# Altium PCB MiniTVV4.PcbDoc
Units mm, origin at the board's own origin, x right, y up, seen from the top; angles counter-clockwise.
Board outline 57.3 x 61.11 mm, 2 copper layers (Top Layer, Bottom Layer), stack 1.571 mm thick; 6 components, 14 nets, 59 pads, 1169 vias.
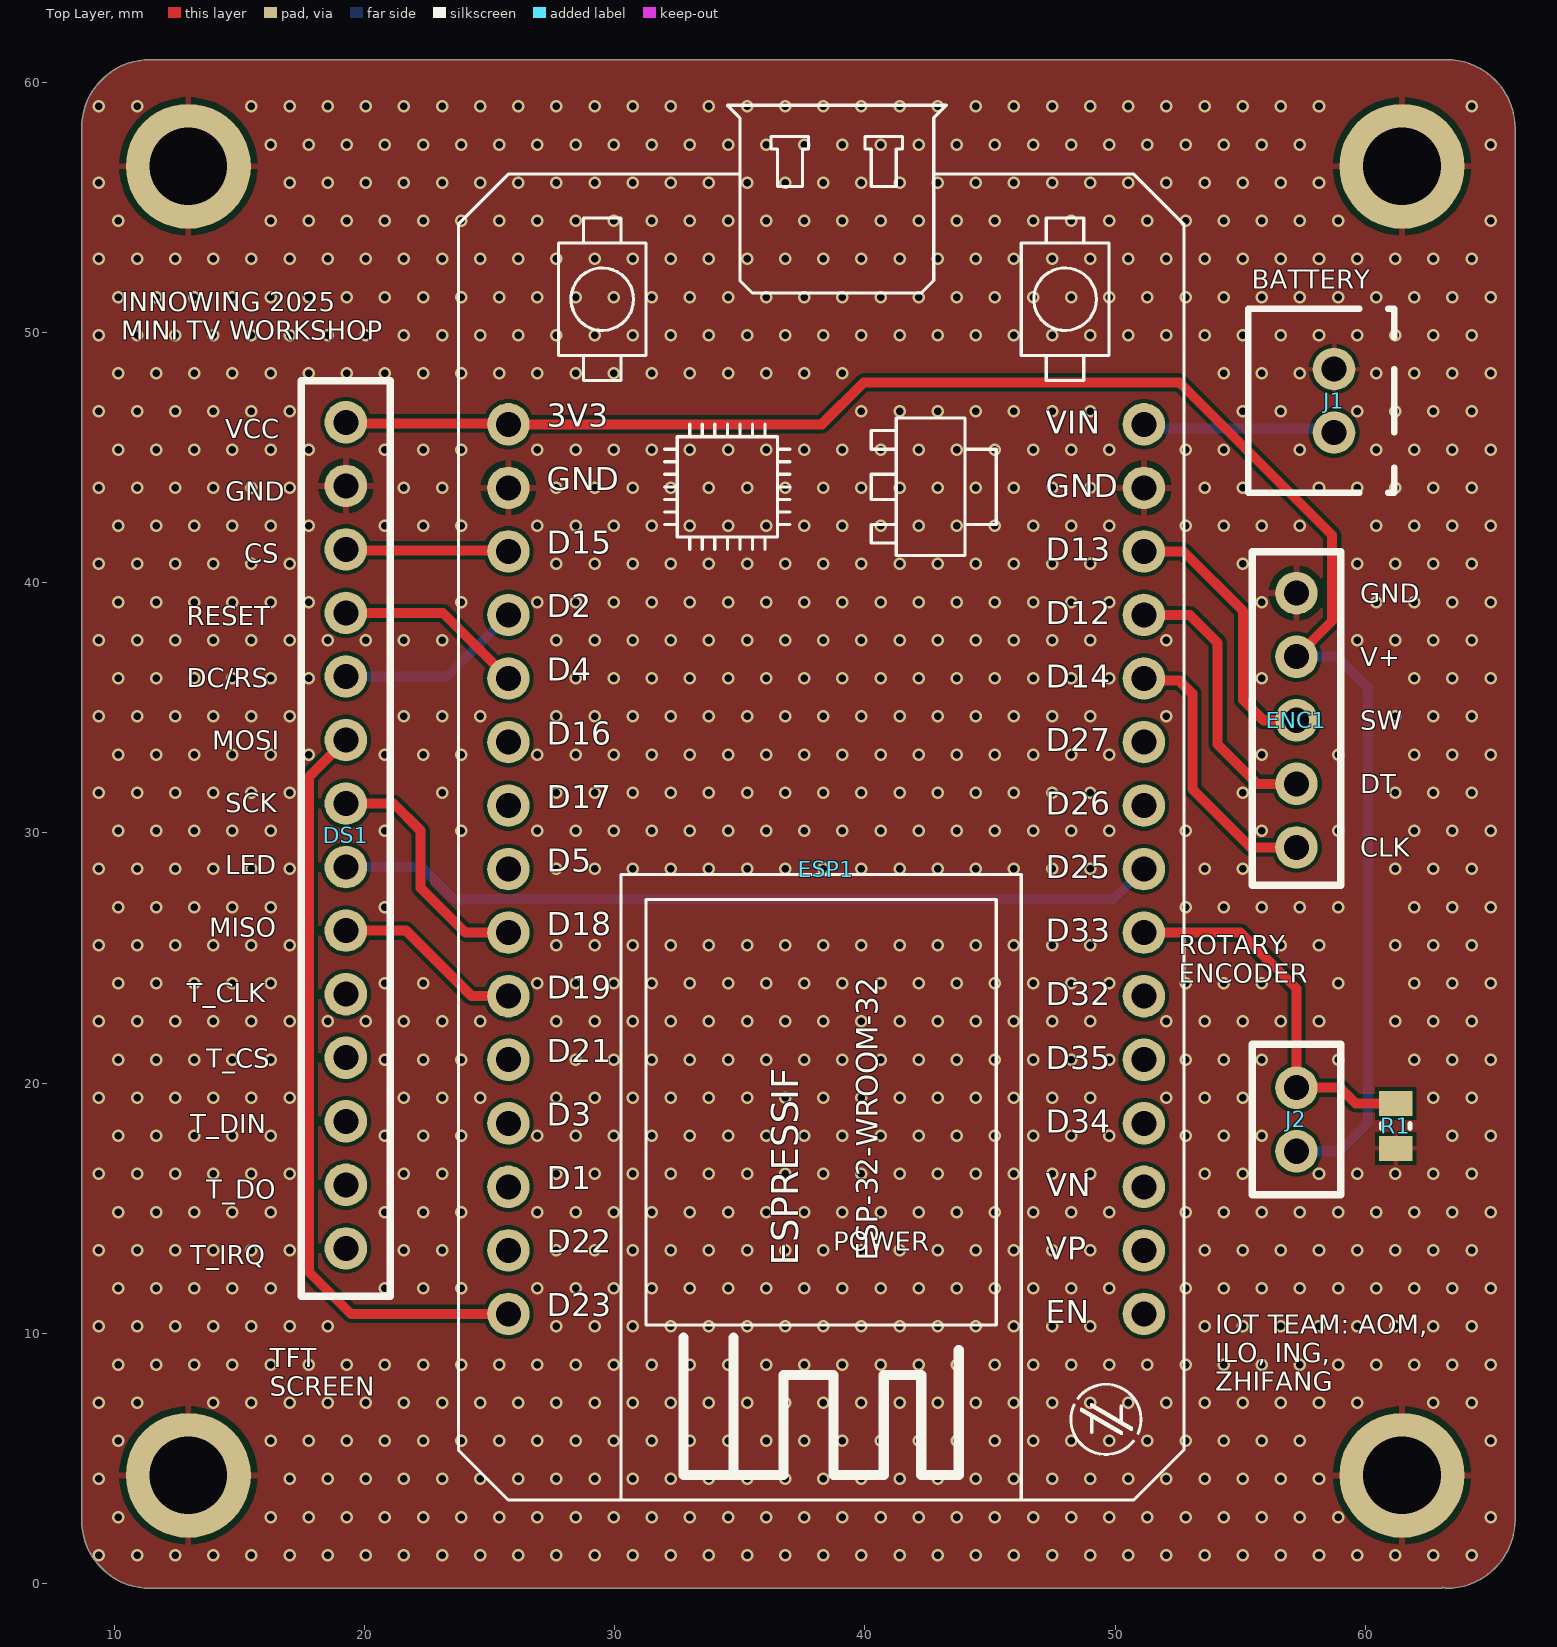
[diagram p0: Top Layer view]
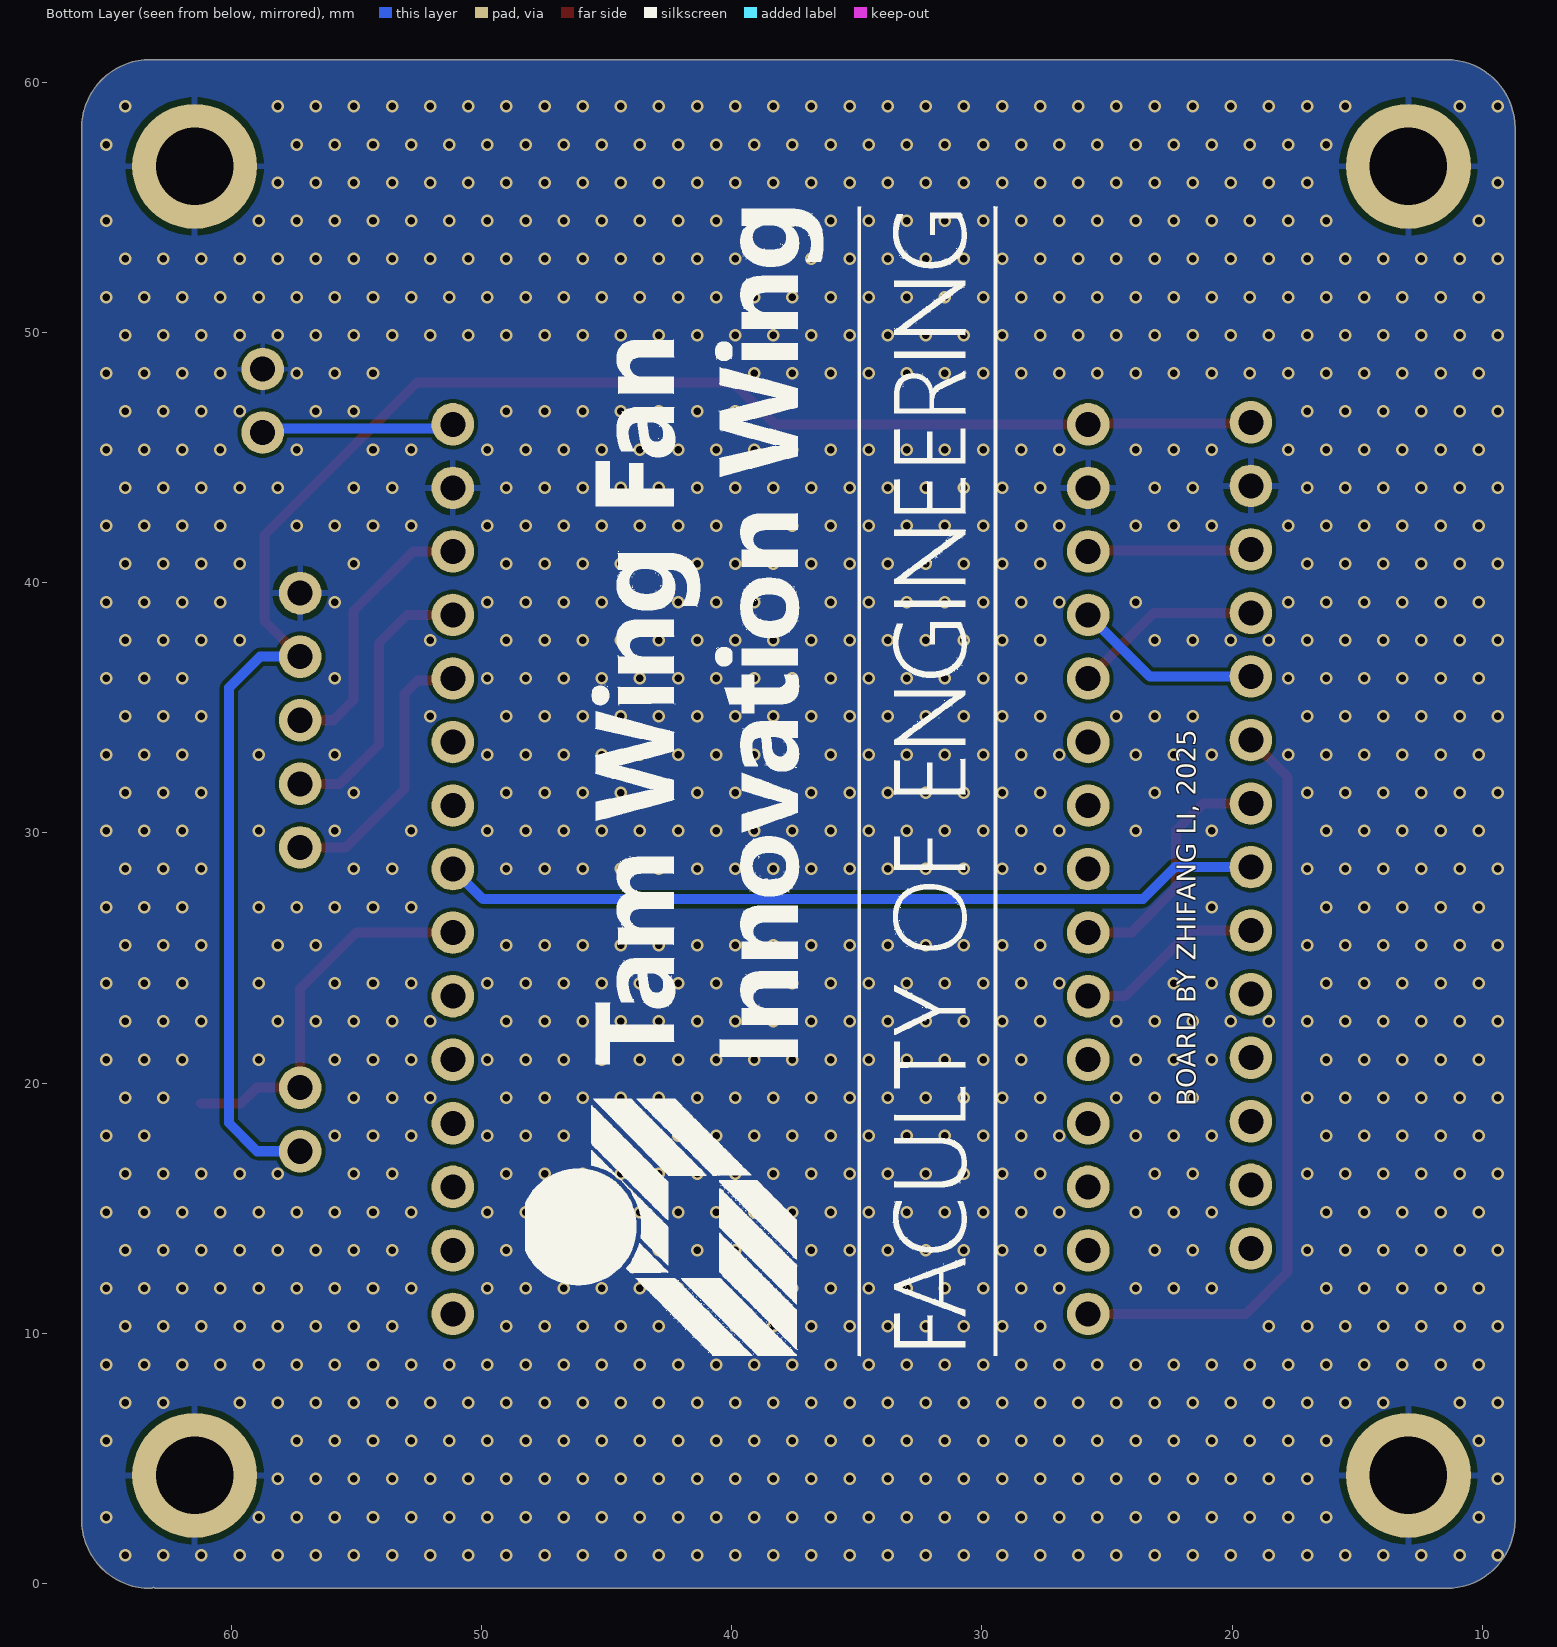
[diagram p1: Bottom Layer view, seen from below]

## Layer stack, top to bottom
Top Solder: solder mask 0.0102, Solder Resist, Dk 3.5
Top Layer: signal copper 0.0356
Dielectric 1: dielectric 1.5, FR-4, Dk 4.8
Bottom Layer: signal copper 0.0356
Bottom Solder: solder mask 0.0102, Solder Resist, Dk 3.5

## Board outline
8.69,2.54 ccw(c11.43,2.54) 11.43,-0.2 62.992,-0.2 ccw(c62.992,0) 63.119,-0.155 ccw(c63.246,0) 63.246,-0.2 ccw(c63.246,2.54) 65.986,2.539 65.986,2.54 65.986,58.166 65.986,58.167 ccw(c63.246,58.166) 63.246,60.906 11.43,60.906 ccw(c11.43,58.166) 8.69,58.166

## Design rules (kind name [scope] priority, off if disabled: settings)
Clearance [All] p1: gap=0.15 ignorepadtopadclearanceinfootprint=FALSE
DiffPairsRouting [All] p1: maxlimit=1 minlimit=0.127 mostfreqgap=0.2 toplayer_minwidth=0.127 toplayer_maxwidth=0.2 toplayer_prefwidth=0.2 bottomlayer_minwidth=0.127 bottomlayer_maxwidth=0.2 bottomlayer_prefwidth=0.2 maxuncoupledlength=12.7
Height [All] p1: minheight=0 maxheight=500 prefheight=12.7
HoleSize [All] p1: absolutevalues=TRUE maxlimit=6.3 minlimit=0.025 maxpercent=80.000 minpercent=20.000
MinimumSolderMaskSliver [All] p1: minsoldermaskwidth=0.04
PolygonConnect CertainComponents [InComponent('C0','C00') vs InNet('GND')] p1: connectstyle=Direct reliefconductorwidth=0.2 reliefentries=4 polygonreliefangle="90 Angle" airgapwidth=0.2 // force certain component to be conencted with relieft connection
PolygonConnect GND [InNet('GND')] p2: thpad.connectstyle=Relief thpad.reliefconductorwidth=0.2 thpad.reliefentries=4 thpad.polygonreliefangle="90 Angle" thpad.airgapwidth=0.15 smdpad.connectstyle=Relief smdpad.reliefconductorwidth=0.2 smdpad.reliefentries=4 smdpad.polygonreliefangle="90 Angle" smdpad.airgapwidth=0.15 via.connectstyle=Direct via.reliefconductorwidth=0.254 via.reliefentries=4 via.polygonreliefangle="90 Angle" via.airgapwidth=0.254
PolygonConnect [All] p3: connectstyle=Direct reliefconductorwidth=0.3 reliefentries=4 polygonreliefangle="90 Angle" airgapwidth=0.127
RoutingVias [All] p1: holewidth=0.3 width=0.5 viastyle="Through Hole" minholewidth=0.3 minwidth=0.5 maxholewidth=6 maxwidth=6.3
SilkToSilkClearance [All] p1: silktosilkclearance=0.04
SilkToSolderMaskClearance [IsPad] p1: minsilkscreentomaskgap=0.04 clearancetoexposedcopper=TRUE
SolderMaskExpansion [All] p1: expansion=0.102 istentingtop=FALSE
SupplyNets "Schematic Supply Nets" [InNet('5V')] p1: voltage=0.000
SupplyNets "Schematic Supply Nets_4" [InNet('3V3')] p2: voltage=0.000
SupplyNets "Schematic Supply Nets_3" [InNet('GND')] p3: voltage=0.000
Width [All] p1: maxlimit=3 minlimit=0.127 preferedwidth=0.2
24 further rules are at their usual default settings.

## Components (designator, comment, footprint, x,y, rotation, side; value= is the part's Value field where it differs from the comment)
DS1 "3.5inch TFT Display" "3.5inch SPI Display" 19.25,46.41 r0 top
ENC1 "Rotary Encoder" "Rotary Encoder" 57.25,29.42 r180 top
ESP1 "https://github.com/shridattdudhat" ESP32-DEVKITV1 25.75,46.33 r270 top
J1 "JST_XH_2P_2.54mm" JST_XH_2P_2.54mm 58.75,47.27 r90 top
J2 "Undifferentiated Pins" "2-Pin 2.54mm" 57.25,18.542 r90 top
R1 "10k 0805" RESC2013X60X35NL10T20 61.214,18.288 r90 top

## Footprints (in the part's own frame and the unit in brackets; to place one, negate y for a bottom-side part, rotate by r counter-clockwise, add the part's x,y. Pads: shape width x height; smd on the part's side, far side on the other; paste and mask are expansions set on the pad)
"2-Pin 2.54mm" [mm]
  round 1.7 hole 1 paste-2539.97 mask+0.051: 1(-1.27,0) 2(1.27,0)
  silkscreen extent -3,-1.78 3,1.78
"3.5inch SPI Display" [mm]
  round 1.7 hole 1: 1(0,0) 2(0,-2.54) 3(0,-5.08) 4(0,-7.62) 5(0,-10.16) 6(0,-12.7) 7(0,-15.24) 8(0,-17.78) 9(0,-20.32) 10(0,-22.86) 11(0,-25.4) 12(0,-27.94) 13(0,-30.48) 14(0,-33.02)
  silkscreen extent -1.78,-34.92 1.78,1.65
ESP32-DEVKITV1 [mm]
  round 1.7 hole 1: 3V3(0,0) D1(30.48,0) D2(7.62,0) D3(27.94,0) D4(10.16,0) D5(17.78,0) D12(7.62,25.4) D13(5.08,25.4) D14(10.16,25.4) D15(5.08,0) D16(12.7,0) D17(15.24,0) D18(20.32,0) D19(22.86,0) D21(25.4,0) D22(33.02,0) D23(35.56,0) D25(17.78,25.4) D26(15.24,25.4) D27(12.7,25.4) D32(22.86,25.4) D33(20.32,25.4) D34(27.94,25.4) D35(25.4,25.4) EN(35.56,25.4) GND(2.54,25.4) GND@1(2.54,0) VIN(0,25.4) VN(30.48,25.4) VP(33.02,25.4)
  silkscreen extent -12.75,-2 43,27
JST_XH_2P_2.54mm [mm]
  round 1.7 hole 1 paste-2539.97 mask+0.051: 1(-1.27,0) 2(1.27,0)
  silkscreen extent -3.68,-2.41 3.68,3.43
RESC2013X60X35NL10T20 [mm] "Chip Resistor, 2-Leads, Body 2.00x1.25mm, IPC Medium Density"
  rect 1x1.35 smd: 1(-0.9,0) 2(0.9,0)
  silkscreen extent -0.1,-0.58 0.1,0.58, body extent -1.05,-0.67 1.05,0.67, height 0.6
"Rotary Encoder" [mm]
  round 1.7 hole 1: 1(0,0) 2(0,-2.54) 3(0,-5.08) 4(0,-7.62) 5(0,-10.16)
  silkscreen extent -1.78,-11.81 1.78,1.52

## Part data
ESP1: library part ESP32DEVKITV1, Package=ESP32-DEVKITV1
J2: library part "SPST 2-Pin"
R1: library part CMP-2001-04523-1, Manufacturer=Yageo, Part Number=RC0805FR-104K7L

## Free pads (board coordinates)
  round 5 hole 3.1: MNT(12.954,4.318) MNT(12.954,56.642) MNT(61.468,4.318) MNT(61.468,56.642)

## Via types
v1: diameter 0.5, hole 0.3, Top Layer to Bottom Layer, tented both sides, 1169 vias

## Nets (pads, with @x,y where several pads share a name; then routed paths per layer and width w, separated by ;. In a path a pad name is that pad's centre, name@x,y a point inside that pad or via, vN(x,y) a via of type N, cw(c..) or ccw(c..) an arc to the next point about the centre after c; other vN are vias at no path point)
3V3: DS1.1 ENC1.4 ESP1.3V3 J2.1 | length 72.2
  Top Layer w0.4: DS1.1 19.29,46.37 25.71,46.37 ESP1.3V3 38.274,46.33 39.95,48.006 52.578,48.006 58.674,41.91 58.674,38.464 ENC1.4
  Bottom Layer w0.4: J2.1 58.972,17.272 60.1,18.4 60.1,35.8 58.86,37.04 ENC1.4
5V: ESP1.VIN J1.1 | length 7.7
  Bottom Layer w0.4: ESP1.VIN 51.315,46.165 58.585,46.165 J1.1
GND: DS1.2 ENC1.5 ESP1.GND ESP1.GND@1 J1.2 pad.MNT R1.1
  other v1: 9.382,1.124 10.906,1.124 12.43,1.124 13.954,1.124 15.478,1.124 17.002,1.124 18.526,1.124 20.05,1.124 21.574,1.124 23.098,1.124 24.622,1.124 26.146,1.124 27.67,1.124 29.194,1.124 30.718,1.124 32.242,1.124 33.766,1.124 35.29,1.124 36.814,1.124 38.338,1.124 39.862,1.124 41.386,1.124 42.91,1.124 44.434,1.124 45.958,1.124 47.482,1.124 49.006,1.124 50.53,1.124 52.054,1.124 53.578,1.124 55.102,1.124 56.626,1.124 58.15,1.124 59.674,1.124 61.198,1.124 62.722,1.124 64.246,1.124 10.144,2.648 16.24,2.648 17.764,2.648 19.288,2.648 20.812,2.648 22.336,2.648 23.86,2.648 25.384,2.648 26.908,2.648 28.432,2.648 29.956,2.648 31.48,2.648 33.004,2.648 34.528,2.648 36.052,2.648 37.576,2.648 39.1,2.648 40.624,2.648 42.148,2.648 43.672,2.648 45.196,2.648 46.72,2.648 48.244,2.648 49.768,2.648 51.292,2.648 52.816,2.648 54.34,2.648 55.864,2.648 57.388,2.648 58.912,2.648 65.008,2.648 9.382,4.172 17.002,4.172 18.526,4.172 20.05,4.172 21.574,4.172 23.098,4.172 24.622,4.172 26.146,4.172 27.67,4.172 29.194,4.172 30.718,4.172 32.242,4.172 33.766,4.172 35.29,4.172 36.814,4.172 38.338,4.172 39.862,4.172 41.386,4.172 42.91,4.172 44.434,4.172 45.958,4.172 47.482,4.172 49.006,4.172 50.53,4.172 52.054,4.172 53.578,4.172 55.102,4.172 56.626,4.172 58.15,4.172 10.144,5.696 16.24,5.696 17.764,5.696 19.288,5.696 20.812,5.696 22.336,5.696 23.86,5.696 25.384,5.696 26.908,5.696 28.432,5.696 29.956,5.696 31.48,5.696 33.004,5.696 34.528,5.696 36.052,5.696 37.576,5.696 39.1,5.696 40.624,5.696 42.148,5.696 43.672,5.696 45.196,5.696 46.72,5.696 48.244,5.696 49.768,5.696 51.292,5.696 52.816,5.696 54.34,5.696 55.864,5.696 57.388,5.696 65.008,5.696 9.382,7.22 10.906,7.22 13.954,7.22 15.478,7.22 17.002,7.22 18.526,7.22 20.05,7.22 21.574,7.22 23.098,7.22 24.622,7.22 26.146,7.22 27.67,7.22 29.194,7.22 30.718,7.22 32.242,7.22 33.766,7.22 35.29,7.22 36.814,7.22 38.338,7.22 39.862,7.22 41.386,7.22 42.91,7.22 44.434,7.22 45.958,7.22 47.482,7.22 49.006,7.22 50.53,7.22 52.054,7.22 53.578,7.22 55.102,7.22 56.626,7.22 58.15,7.22 59.674,7.22 62.722,7.22 64.246,7.22 10.144,8.744 11.668,8.744 13.192,8.744 14.716,8.744 16.24,8.744 17.764,8.744 19.288,8.744 20.812,8.744 22.336,8.744 23.86,8.744 25.384,8.744 26.908,8.744 28.432,8.744 29.956,8.744 31.48,8.744 33.004,8.744 34.528,8.744 36.052,8.744 37.576,8.744 39.1,8.744 40.624,8.744 42.148,8.744 43.672,8.744 45.196,8.744 46.72,8.744 48.244,8.744 49.768,8.744 51.292,8.744 52.816,8.744 54.34,8.744 55.864,8.744 57.388,8.744 58.912,8.744 60.436,8.744 61.96,8.744 63.484,8.744 65.008,8.744 9.382,10.268 10.906,10.268 12.43,10.268 13.954,10.268 15.478,10.268 17.002,10.268 18.526,10.268 27.67,10.268 29.194,10.268 30.718,10.268 32.242,10.268 33.766,10.268 35.29,10.268 36.814,10.268 38.338,10.268 39.862,10.268 41.386,10.268 42.91,10.268 44.434,10.268 45.958,10.268 47.482,10.268 49.006,10.268 53.578,10.268 55.102,10.268 56.626,10.268 58.15,10.268 59.674,10.268 61.198,10.268 62.722,10.268 64.246,10.268 10.144,11.792 11.668,11.792 13.192,11.792 14.716,11.792 16.24,11.792 20.812,11.792 22.336,11.792 23.86,11.792 26.908,11.792 28.432,11.792 29.956,11.792 31.48,11.792 33.004,11.792 34.528,11.792 36.052,11.792 37.576,11.792 39.1,11.792 40.624,11.792 42.148,11.792 43.672,11.792 45.196,11.792 46.72,11.792 48.244,11.792 49.768,11.792 52.816,11.792 54.34,11.792 55.864,11.792 57.388,11.792 58.912,11.792 60.436,11.792 61.96,11.792 63.484,11.792 65.008,11.792 9.382,13.316 10.906,13.316 12.43,13.316 13.954,13.316 15.478,13.316 17.002,13.316 21.574,13.316 23.098,13.316 27.67,13.316 29.194,13.316 30.718,13.316 32.242,13.316 33.766,13.316 35.29,13.316 36.814,13.316 38.338,13.316 39.862,13.316 41.386,13.316 42.91,13.316 44.434,13.316 45.958,13.316 47.482,13.316 49.006,13.316 53.578,13.316 55.102,13.316 56.626,13.316 58.15,13.316 59.674,13.316 61.198,13.316 62.722,13.316 64.246,13.316 10.144,14.84 11.668,14.84 13.192,14.84 14.716,14.84 16.24,14.84 20.812,14.84 22.336,14.84 23.86,14.84 26.908,14.84 28.432,14.84 29.956,14.84 31.48,14.84 33.004,14.84 34.528,14.84 36.052,14.84 37.576,14.84 39.1,14.84 40.624,14.84 42.148,14.84 43.672,14.84 45.196,14.84 46.72,14.84 48.244,14.84 49.768,14.84 52.816,14.84 54.34,14.84 55.864,14.84 57.388,14.84 58.912,14.84 60.436,14.84 61.96,14.84 63.484,14.84 65.008,14.84 9.382,16.364 10.906,16.364 12.43,16.364 13.954,16.364 15.478,16.364 17.002,16.364 21.574,16.364 23.098,16.364 27.67,16.364 29.194,16.364 30.718,16.364 32.242,16.364 33.766,16.364 35.29,16.364 36.814,16.364 38.338,16.364 39.862,16.364 41.386,16.364 42.91,16.364 44.434,16.364 45.958,16.364 47.482,16.364 49.006,16.364 53.578,16.364 55.102,16.364 58.15,16.364 59.674,16.364 61.198,16.364 62.722,16.364 64.246,16.364 10.144,17.888 11.668,17.888 13.192,17.888 14.716,17.888 16.24,17.888 20.812,17.888 22.336,17.888 23.86,17.888 26.908,17.888 28.432,17.888 29.956,17.888 31.48,17.888 33.004,17.888 34.528,17.888 36.052,17.888 37.576,17.888 39.1,17.888 40.624,17.888 42.148,17.888 43.672,17.888 45.196,17.888 46.72,17.888 48.244,17.888 49.768,17.888 52.816,17.888 54.34,17.888 55.864,17.888 63.484,17.888 65.008,17.888 9.382,19.412 10.906,19.412 12.43,19.412 13.954,19.412 15.478,19.412 17.002,19.412 21.574,19.412 23.098,19.412 24.622,19.412 27.67,19.412 29.194,19.412 30.718,19.412 32.242,19.412 33.766,19.412 35.29,19.412 36.814,19.412 38.338,19.412 39.862,19.412 41.386,19.412 42.91,19.412 44.434,19.412 45.958,19.412 47.482,19.412 49.006,19.412 52.054,19.412 53.578,19.412 55.102,19.412 62.722,19.412 64.246,19.412 10.144,20.936 11.668,20.936 13.192,20.936 14.716,20.936 16.24,20.936 20.812,20.936 22.336,20.936 23.86,20.936 28.432,20.936 29.956,20.936 31.48,20.936 33.004,20.936 34.528,20.936 36.052,20.936 37.576,20.936 39.1,20.936 40.624,20.936 42.148,20.936 43.672,20.936 45.196,20.936 46.72,20.936 48.244,20.936 49.768,20.936 52.816,20.936 54.34,20.936 55.864,20.936 58.912,20.936 61.96,20.936 63.484,20.936 65.008,20.936 9.382,22.46 10.906,22.46 12.43,22.46 13.954,22.46 15.478,22.46 17.002,22.46 18.526,22.46 20.05,22.46 21.574,22.46 23.098,22.46 24.622,22.46 27.67,22.46 29.194,22.46 30.718,22.46 32.242,22.46 33.766,22.46 35.29,22.46 36.814,22.46 38.338,22.46 39.862,22.46 41.386,22.46 42.91,22.46 44.434,22.46 45.958,22.46 47.482,22.46 49.006,22.46 52.054,22.46 53.578,22.46 55.102,22.46 56.626,22.46 58.15,22.46 61.198,22.46 62.722,22.46 64.246,22.46 10.144,23.984 11.668,23.984 13.192,23.984 14.716,23.984 16.24,23.984 20.812,23.984 22.336,23.984 26.908,23.984 28.432,23.984 29.956,23.984 31.48,23.984 33.004,23.984 34.528,23.984 36.052,23.984 37.576,23.984 39.1,23.984 40.624,23.984 42.148,23.984 43.672,23.984 45.196,23.984 46.72,23.984 48.244,23.984 49.768,23.984 52.816,23.984 54.34,23.984 55.864,23.984 58.912,23.984 61.96,23.984 63.484,23.984 65.008,23.984 9.382,25.508 10.906,25.508 12.43,25.508 13.954,25.508 15.478,25.508 17.002,25.508 27.67,25.508 29.194,25.508 30.718,25.508 32.242,25.508 33.766,25.508 35.29,25.508 36.814,25.508 38.338,25.508 39.862,25.508 41.386,25.508 42.91,25.508 44.434,25.508 45.958,25.508 47.482,25.508 49.006,25.508 56.626,25.508 58.15,25.508 61.198,25.508 62.722,25.508 64.246,25.508 10.144,27.032 11.668,27.032 13.192,27.032 14.716,27.032 16.24,27.032 20.812,27.032 52.816,27.032 54.34,27.032 55.864,27.032 57.388,27.032 58.912,27.032 61.96,27.032 63.484,27.032 65.008,27.032 9.382,28.556 10.906,28.556 12.43,28.556 13.954,28.556 15.478,28.556 17.002,28.556 27.67,28.556 29.194,28.556 30.718,28.556 32.242,28.556 33.766,28.556 35.29,28.556 36.814,28.556 38.338,28.556 39.862,28.556 41.386,28.556 42.91,28.556 44.434,28.556 45.958,28.556 47.482,28.556 49.006,28.556 53.578,28.556 55.102,28.556 61.198,28.556 62.722,28.556 64.246,28.556 10.144,30.08 11.668,30.08 13.192,30.08 14.716,30.08 16.24,30.08 20.812,30.08 23.86,30.08 26.908,30.08 28.432,30.08 29.956,30.08 31.48,30.08 33.004,30.08 34.528,30.08 36.052,30.08 37.576,30.08 39.1,30.08 40.624,30.08 42.148,30.08 43.672,30.08 45.196,30.08 46.72,30.08 48.244,30.08 49.768,30.08 52.816,30.08 55.864,30.08 58.912,30.08 61.96,30.08 63.484,30.08 65.008,30.08 9.382,31.604 10.906,31.604 12.43,31.604 13.954,31.604 15.478,31.604 17.002,31.604 23.098,31.604 27.67,31.604 29.194,31.604 30.718,31.604 32.242,31.604 33.766,31.604 35.29,31.604 36.814,31.604 38.338,31.604 39.862,31.604 41.386,31.604 42.91,31.604 44.434,31.604 45.958,31.604 47.482,31.604 49.006,31.604 55.102,31.604 61.198,31.604 62.722,31.604 64.246,31.604 10.144,33.128 11.668,33.128 13.192,33.128 14.716,33.128 16.24,33.128 17.764,33.128 20.812,33.128 22.336,33.128 23.86,33.128 26.908,33.128 28.432,33.128 29.956,33.128 31.48,33.128 33.004,33.128 34.528,33.128 36.052,33.128 37.576,33.128 39.1,33.128 40.624,33.128 42.148,33.128 43.672,33.128 45.196,33.128 46.72,33.128 48.244,33.128 49.768,33.128 55.864,33.128 58.912,33.128 61.96,33.128 63.484,33.128 65.008,33.128 9.382,34.652 10.906,34.652 12.43,34.652 13.954,34.652 15.478,34.652 17.002,34.652 21.574,34.652 23.098,34.652 24.622,34.652 27.67,34.652 29.194,34.652 30.718,34.652 32.242,34.652 33.766,34.652 35.29,34.652 36.814,34.652 38.338,34.652 39.862,34.652 41.386,34.652 42.91,34.652 44.434,34.652 45.958,34.652 47.482,34.652 49.006,34.652 52.054,34.652 61.198,34.652 62.722,34.652 64.246,34.652 10.144,36.176 11.668,36.176 13.192,36.176 14.716,36.176 16.24,36.176 17.764,36.176 28.432,36.176 29.956,36.176 31.48,36.176 33.004,36.176 34.528,36.176 36.052,36.176 37.576,36.176 39.1,36.176 40.624,36.176 42.148,36.176 43.672,36.176 45.196,36.176 46.72,36.176 48.244,36.176 49.768,36.176 55.864,36.176 61.96,36.176 63.484,36.176 65.008,36.176 9.382,37.7 10.906,37.7 12.43,37.7 13.954,37.7 15.478,37.7 17.002,37.7 18.526,37.7 20.05,37.7 21.574,37.7 23.098,37.7 27.67,37.7 29.194,37.7 30.718,37.7 32.242,37.7 33.766,37.7 35.29,37.7 36.814,37.7 38.338,37.7 39.862,37.7 41.386,37.7 42.91,37.7 44.434,37.7 45.958,37.7 47.482,37.7 49.006,37.7 52.054,37.7 59.674,37.7 61.198,37.7 62.722,37.7 64.246,37.7 10.144,39.224 11.668,39.224 13.192,39.224 14.716,39.224 16.24,39.224 17.764,39.224 23.86,39.224 26.908,39.224 28.432,39.224 29.956,39.224 31.48,39.224 33.004,39.224 34.528,39.224 36.052,39.224 37.576,39.224 39.1,39.224 40.624,39.224 42.148,39.224 43.672,39.224 45.196,39.224 46.72,39.224 48.244,39.224 49.768,39.224 55.864,39.224 60.436,39.224 61.96,39.224 63.484,39.224 65.008,39.224 9.382,40.748 10.906,40.748 12.43,40.748 13.954,40.748 15.478,40.748 17.002,40.748 27.67,40.748 29.194,40.748 30.718,40.748 32.242,40.748 33.766,40.748 35.29,40.748 36.814,40.748 38.338,40.748 39.862,40.748 41.386,40.748 42.91,40.748 44.434,40.748 45.958,40.748 47.482,40.748 49.006,40.748 55.102,40.748 59.674,40.748 61.198,40.748 62.722,40.748 64.246,40.748 10.144,42.272 11.668,42.272 13.192,42.272 14.716,42.272 16.24,42.272 17.764,42.272 20.812,42.272 22.336,42.272 23.86,42.272 26.908,42.272 28.432,42.272 29.956,42.272 31.48,42.272 33.004,42.272 34.528,42.272 36.052,42.272 37.576,42.272 39.1,42.272 40.624,42.272 42.148,42.272 43.672,42.272 45.196,42.272 46.72,42.272 48.244,42.272 49.768,42.272 52.816,42.272 54.34,42.272 55.864,42.272 57.388,42.272 60.436,42.272 61.96,42.272 63.484,42.272 65.008,42.272 9.382,43.796 10.906,43.796 12.43,43.796 13.954,43.796 15.478,43.796 17.002,43.796 21.574,43.796 23.098,43.796 27.67,43.796 29.194,43.796 30.718,43.796 32.242,43.796 33.766,43.796 35.29,43.796 36.814,43.796 38.338,43.796 39.862,43.796 41.386,43.796 42.91,43.796 44.434,43.796 45.958,43.796 47.482,43.796 49.006,43.796 53.578,43.796 55.102,43.796 58.15,43.796 59.674,43.796 61.198,43.796 62.722,43.796 64.246,43.796 10.144,45.32 11.668,45.32 13.192,45.32 14.716,45.32 16.24,45.32 17.764,45.32 20.812,45.32 22.336,45.32 23.86,45.32 26.908,45.32 28.432,45.32 29.956,45.32 31.48,45.32 33.004,45.32 34.528,45.32 36.052,45.32 37.576,45.32 39.1,45.32 40.624,45.32 42.148,45.32 43.672,45.32 45.196,45.32 46.72,45.32 48.244,45.32 49.768,45.32 52.816,45.32 54.34,45.32 57.388,45.32 60.436,45.32 61.96,45.32 63.484,45.32 65.008,45.32 9.382,46.844 10.906,46.844 12.43,46.844 13.954,46.844 15.478,46.844 17.002,46.844 39.862,46.844 41.386,46.844 42.91,46.844 44.434,46.844 45.958,46.844 47.482,46.844 49.006,46.844 55.102,46.844 56.626,46.844 59.674,46.844 61.198,46.844 62.722,46.844 64.246,46.844 10.144,48.368 11.668,48.368 13.192,48.368 14.716,48.368 16.24,48.368 17.764,48.368 19.288,48.368 20.812,48.368 22.336,48.368 23.86,48.368 25.384,48.368 26.908,48.368 28.432,48.368 29.956,48.368 31.48,48.368 33.004,48.368 34.528,48.368 36.052,48.368 37.576,48.368 39.1,48.368 54.34,48.368 55.864,48.368 57.388,48.368 60.436,48.368 61.96,48.368 63.484,48.368 65.008,48.368 9.382,49.892 10.906,49.892 12.43,49.892 13.954,49.892 15.478,49.892 17.002,49.892 18.526,49.892 20.05,49.892 21.574,49.892 23.098,49.892 24.622,49.892 26.146,49.892 27.67,49.892 29.194,49.892 30.718,49.892 32.242,49.892 33.766,49.892 35.29,49.892 36.814,49.892 38.338,49.892 39.862,49.892 41.386,49.892 42.91,49.892 44.434,49.892 45.958,49.892 47.482,49.892 49.006,49.892 50.53,49.892 52.054,49.892 53.578,49.892 55.102,49.892 56.626,49.892 58.15,49.892 59.674,49.892 61.198,49.892 62.722,49.892 64.246,49.892 10.144,51.416 11.668,51.416 13.192,51.416 14.716,51.416 16.24,51.416 17.764,51.416 19.288,51.416 20.812,51.416 22.336,51.416 23.86,51.416 25.384,51.416 26.908,51.416 28.432,51.416 29.956,51.416 31.48,51.416 33.004,51.416 34.528,51.416 36.052,51.416 37.576,51.416 39.1,51.416 40.624,51.416 42.148,51.416 43.672,51.416 45.196,51.416 46.72,51.416 48.244,51.416 49.768,51.416 51.292,51.416 52.816,51.416 54.34,51.416 55.864,51.416 57.388,51.416 58.912,51.416 60.436,51.416 61.96,51.416 63.484,51.416 65.008,51.416 9.382,52.94 10.906,52.94 12.43,52.94 13.954,52.94 15.478,52.94 17.002,52.94 18.526,52.94 20.05,52.94 21.574,52.94 23.098,52.94 24.622,52.94 26.146,52.94 27.67,52.94 29.194,52.94 30.718,52.94 32.242,52.94 33.766,52.94 35.29,52.94 36.814,52.94 38.338,52.94 39.862,52.94 41.386,52.94 42.91,52.94 44.434,52.94 45.958,52.94 47.482,52.94 49.006,52.94 50.53,52.94 52.054,52.94 53.578,52.94 55.102,52.94 56.626,52.94 58.15,52.94 59.674,52.94 61.198,52.94 62.722,52.94 64.246,52.94 10.144,54.464 16.24,54.464 17.764,54.464 19.288,54.464 20.812,54.464 22.336,54.464 23.86,54.464 25.384,54.464 26.908,54.464 28.432,54.464 29.956,54.464 31.48,54.464 33.004,54.464 34.528,54.464 36.052,54.464 37.576,54.464 39.1,54.464 40.624,54.464 42.148,54.464 43.672,54.464 45.196,54.464 46.72,54.464 48.244,54.464 49.768,54.464 51.292,54.464 52.816,54.464 54.34,54.464 55.864,54.464 57.388,54.464 58.912,54.464 65.008,54.464 9.382,55.988 17.002,55.988 18.526,55.988 20.05,55.988 21.574,55.988 23.098,55.988 24.622,55.988 26.146,55.988 27.67,55.988 29.194,55.988 30.718,55.988 32.242,55.988 33.766,55.988 35.29,55.988 36.814,55.988 38.338,55.988 39.862,55.988 41.386,55.988 42.91,55.988 44.434,55.988 45.958,55.988 47.482,55.988 49.006,55.988 50.53,55.988 52.054,55.988 53.578,55.988 55.102,55.988 56.626,55.988 58.15,55.988 16.24,57.512 17.764,57.512 19.288,57.512 20.812,57.512 22.336,57.512 23.86,57.512 25.384,57.512 26.908,57.512 28.432,57.512 29.956,57.512 31.48,57.512 33.004,57.512 34.528,57.512 36.052,57.512 37.576,57.512 39.1,57.512 40.624,57.512 42.148,57.512 43.672,57.512 45.196,57.512 46.72,57.512 48.244,57.512 49.768,57.512 51.292,57.512 52.816,57.512 54.34,57.512 55.864,57.512 57.388,57.512 65.008,57.512 9.382,59.036 10.906,59.036 15.478,59.036 17.002,59.036 18.526,59.036 20.05,59.036 21.574,59.036 23.098,59.036 24.622,59.036 26.146,59.036 27.67,59.036 29.194,59.036 30.718,59.036 32.242,59.036 33.766,59.036 35.29,59.036 36.814,59.036 38.338,59.036 39.862,59.036 41.386,59.036 42.91,59.036 44.434,59.036 45.958,59.036 47.482,59.036 49.006,59.036 50.53,59.036 52.054,59.036 53.578,59.036 55.102,59.036 56.626,59.036 58.15,59.036 64.246,59.036
NetDS1_3: DS1.3 ESP1.D15 | length 6.5
  Top Layer w0.4: DS1.3 19.29,41.29 25.71,41.29 ESP1.D15
NetDS1_4: DS1.4 ESP1.D4 | length 7.6
  Top Layer w0.4: DS1.4 23.13,38.79 ESP1.D4
NetDS1_5: DS1.5 ESP1.D2 | length 7.5
  Bottom Layer w0.4: DS1.5 23.29,36.25 ESP1.D2
NetDS1_6: DS1.6 ESP1.D23 | length 30.5
  Top Layer w0.4: DS1.6 17.78,32.24 17.78,12.446 19.456,10.77 ESP1.D23
NetDS1_7: DS1.7 ESP1.D18 | length 10
  Top Layer w0.4: DS1.7 21.154,31.17 22.241,30.083 22.241,27.797 24.028,26.01 ESP1.D18
NetDS1_8: DS1.8 ESP1.D25 | length 32.9
  Bottom Layer w0.4: DS1.8 22.284,28.63 23.564,27.35 49.95,27.35 ESP1.D25
NetDS1_9: DS1.9 ESP1.D19 | length 7.6
  Top Layer w0.4: DS1.9 21.662,26.09 24.282,23.47 ESP1.D19
NetENC1_1: ENC1.1 ESP1.D14 | length 11.1
  Top Layer w0.4: ESP1.D14 51.239,36.081 52.565,36.081 53.086,35.56 53.086,31.75 55.416,29.42 ENC1.1
NetENC1_2: ENC1.2 ESP1.D12 | length 11.3
  Top Layer w0.4: ESP1.D12 52.984,38.71 54.102,37.592 54.102,33.528 55.67,31.96 ENC1.2
NetENC1_3: ENC1.3 ESP1.D13 | length 11
  Top Layer w0.4: ESP1.D13 52.73,41.25 55.118,38.862 55.118,35.306 55.924,34.5 ENC1.3
NetESP1_D33: ESP1.D33 J2.2 R1.2 | length 15.2
  Top Layer w0.4: ESP1.D33 55.016,26.01 57.25,23.776 J2.2 58.988,19.812 59.612,19.188 R1.2
pads on no net: DS1.10 DS1.11 DS1.12 DS1.13 DS1.14 ESP1.D1 ESP1.D3 ESP1.D5 ESP1.D16 ESP1.D17 ESP1.D21 ESP1.D22 ESP1.D26 ESP1.D27 ESP1.D32 ESP1.D34 ESP1.D35 ESP1.EN ESP1.VN ESP1.VP

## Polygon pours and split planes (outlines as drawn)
GND on Top Layer "NONET_L-01_P-001" (solid, pour order 0): 8.69,2.54 ccw(c11.43,2.54) 11.43,-0.2 62.992,-0.2 ccw(c62.992,0) 63.119,-0.155 ccw(c63.246,0) 63.246,-0.2 ccw(c63.246,2.54) 65.986,2.539 65.986,2.54 65.986,58.166 65.986,58.167 ccw(c63.246,58.166) 63.246,60.906 11.43,60.906 ccw(c11.43,58.166) 8.69,58.166
GND on Bottom Layer "NONET_L-01_P-001" (solid, pour order 1): 8.69,2.54 ccw(c11.43,2.54) 11.43,-0.2 62.992,-0.2 ccw(c62.992,0) 63.119,-0.155 ccw(c63.246,0) 63.246,-0.2 ccw(c63.246,2.54) 65.986,2.539 65.986,2.54 65.986,58.166 65.986,58.167 ccw(c63.246,58.166) 63.246,60.906 11.43,60.906 ccw(c11.43,58.166) 8.69,58.166

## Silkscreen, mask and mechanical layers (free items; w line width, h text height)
Top Overlay:
  drawing of 4 lines, arcs and shapes, not listed
  text "BATTERY" at 55.457,51.75 h0.76
  text "INNOWING 2025 / MINI TV WORKSHOP" at 10.275,49.7 h0.76
  text "ROTARY / ENCODER" at 52.552,24 h0.76
  text "POWER" at 38.732,13.3 h0.76
  text "IOT TEAM: AOM, / ILO, ING, / ZHIFANG" at 54,7.7 h0.76
  text "TFT / SCREEN" at 16.207,7.5 h0.76
Bottom Overlay:
  drawing of 364 lines, arcs and shapes, not listed
  text "BOARD BY ZHIFANG LI, 2025" at 21.444,19.073 h0.76 r270
Mechanical 1:
  lines w0.4: 62.992,0 58.674,0 11.43,0 cw(c11.43,2.54) 8.89,2.54 8.89,16.002 8.89,58.166 cw(c11.43,58.166) 11.43,60.706 33.782,60.706 38.862,60.706 63.246,60.706 cw(c63.246,58.166) 65.786,58.166 65.786,47.244 65.786,2.54 cw(c63.246,2.54) 63.246,0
